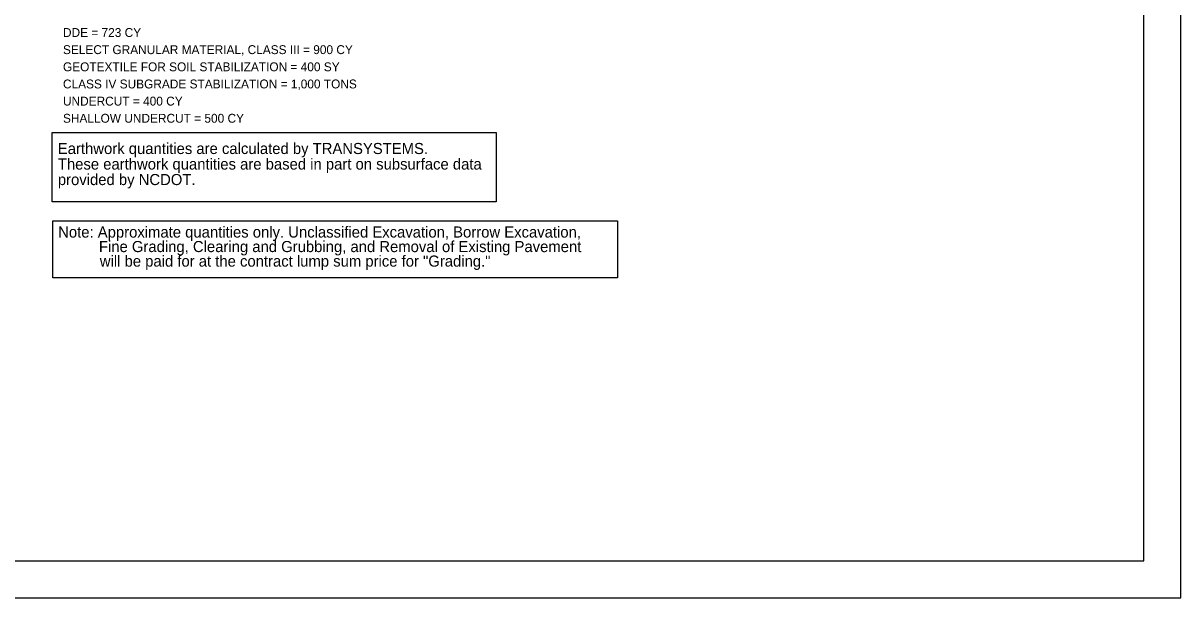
# Model space of a CAD drawing. Extents: x 573680 to 575380, y -53324 to -52224.
# Drawn here: x 574597 to 575380, y -53324 to -52936 of the extents above; entities that cross this region are included whole.
import ezdxf

# ---------------------------------------------------------------- set-up
doc = ezdxf.new("R2010")
doc.units = 0
for name, color, linetype in [('Old_Level_1', 7, 'Continuous'), ('Prop Grid Mask', 7, 'Continuous'), ('Prop XSC Text', 7, 'Continuous'), ('Sheet Plan And Profile CELL', 7, 'Continuous'), ('Sheet Plot Border Outside CELL', 7, 'Continuous'), ('Sheet Summary Earthwork CELL', 7, 'Continuous')]:
    doc.layers.add(name, color=color, linetype=linetype)

msp = doc.modelspace()

# ---------------------------------------------------------------- linework, layer by layer
at = {"layer": 'Prop Grid Mask'}
msp.add_lwpolyline([(574617.29, -53069.5), (574998.9, -53069.5), (574998.9, -53107.94), (574617.29, -53107.94)], close=True, dxfattribs=at)
at = {"layer": 'Sheet Plan And Profile CELL'}
msp.add_lwpolyline([(575354.86, -52249.31), (573854.86, -52249.31), (573854.86, -53299.31), (575354.86, -53299.31)], close=True, dxfattribs=at)
at = {"layer": 'Sheet Plot Border Outside CELL'}
msp.add_lwpolyline([(573679.86, -53324.31), (575379.86, -53324.31), (575379.86, -52224.31), (573679.86, -52224.31)], close=True, dxfattribs=at)
at = {"layer": 'Sheet Summary Earthwork CELL'}
msp.add_lwpolyline([(574616.91, -53009.68), (574916.97, -53009.68), (574916.97, -53056.52), (574616.91, -53056.52)], close=True, dxfattribs=at)

# ---------------------------------------------------------------- texts
at = {"layer": 'Old_Level_1'}
for s, p in [('DDE = 723 CY', (574624.12, -52945.05)), ('SELECT GRANULAR MATERIAL, CLASS III = 900 CY', (574624.12, -52956.65)), ('GEOTEXTILE FOR SOIL STABILIZATION = 400 SY', (574624.12, -52968.25)), ('CLASS IV SUBGRADE STABILIZATION = 1,000 TONS', (574624.12, -52979.85)), ('UNDERCUT = 400 CY', (574624.12, -52991.45)), ('SHALLOW UNDERCUT = 500 CY', (574624.12, -53003.05))]:
    msp.add_text(s, height=6, rotation=359.99998, dxfattribs=at).set_placement(p)
at = {"layer": 'Prop XSC Text'}
for s, p in [('Note: Approximate quantities only. Unclassified Excavation, Borrow Excavation, ', (574620.88, -53080.7)), ('Fine Grading, Clearing and Grubbing, and Removal of Existing Pavement', (574648.43, -53090.53)), ('will be paid for at the contract lump sum price for "Grading."', (574649.04, -53100.36))]:
    msp.add_text(s, height=7.5, dxfattribs=at).set_placement(p)
at = {"layer": 'Sheet Summary Earthwork CELL'}
for s, p in [('Earthwork quantities are calculated by TRANSYSTEMS. ', (574620.66, -53024.22)), ('These earthwork quantities are based in part on subsurface data ', (574620.66, -53034.72)), ('provided by NCDOT.', (574620.66, -53045.22))]:
    msp.add_text(s, height=7.5, dxfattribs=at).set_placement(p)

doc.saveas('drawing.dxf')
